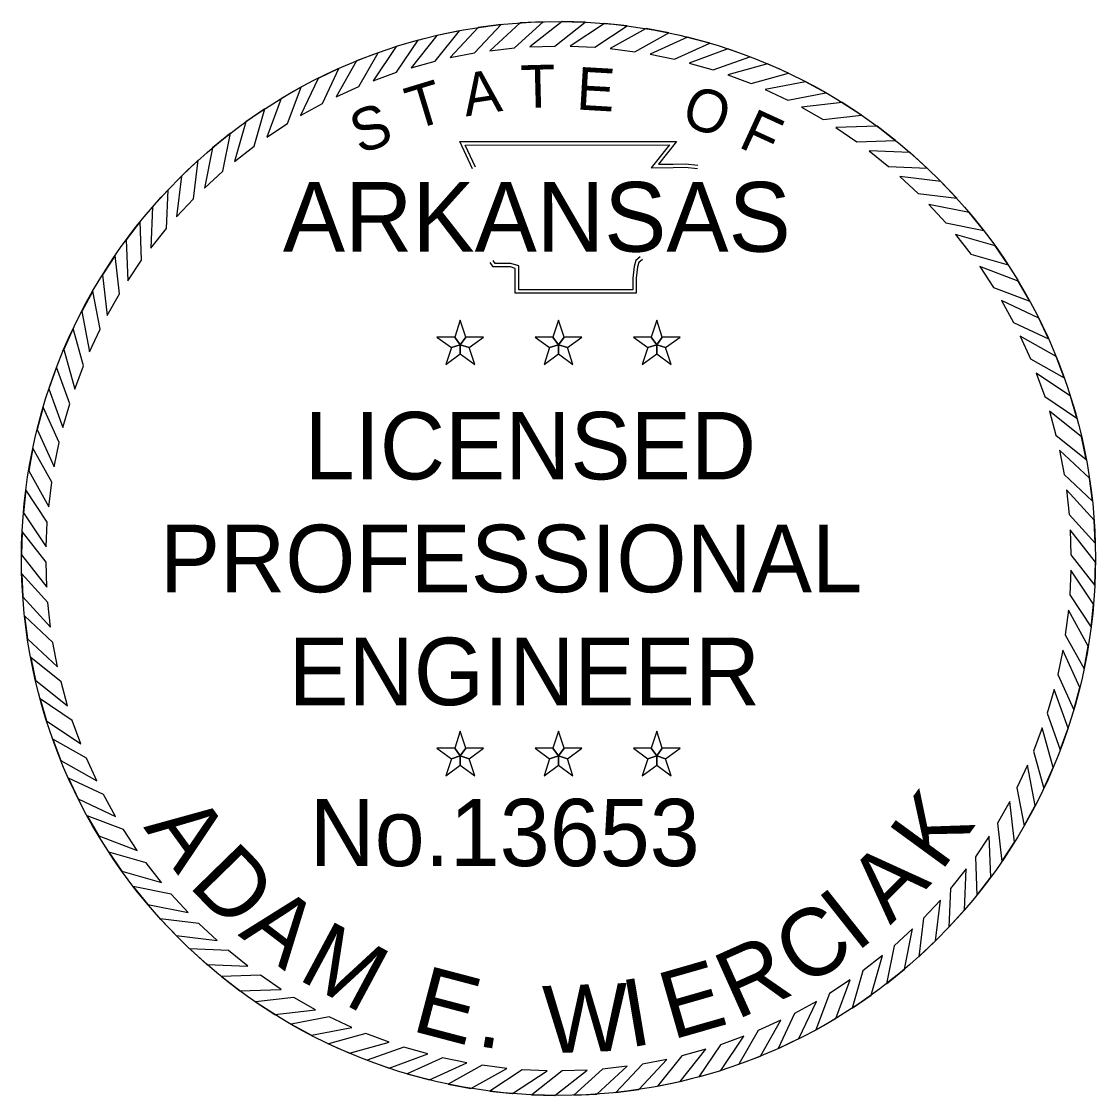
# Model space of a CAD drawing. Extents: x 0 to 19, y -0.6 to 11.3.
# Drawn here: x 17.822 to 19.022, y 6.31 to 7.51 of the extents above; entities that cross this region are included whole.
import ezdxf

# ---------------------------------------------------------------- set-up
doc = ezdxf.new("R2010")
doc.units = 0
for name, color, linetype in [('G-ANNO-STMP', 7, 'Continuous'), ('G-No Plot-Stamp-1', 7, 'Continuous'), ('G-No Plot-Stamp-2', 7, 'Continuous')]:
    doc.layers.add(name, color=color, linetype=linetype)

msp = doc.modelspace()

# ---------------------------------------------------------------- linework, layer by layer
at = {"layer": 'G-ANNO-STMP'}
for points in [[(18.3581, 7.5062), (18.3325, 7.5029), (18.3011, 7.4693), (18.3285, 7.4745)], [(18.4051, 7.5094), (18.3793, 7.5081), (18.3454, 7.477), (18.3731, 7.4801)], [(18.4522, 7.5089), (18.4264, 7.5096), (18.3902, 7.4813), (18.418, 7.4822)], [(18.4991, 7.5047), (18.4735, 7.5074), (18.4351, 7.4821), (18.463, 7.4808)], [(18.5456, 7.4968), (18.5202, 7.5016), (18.48, 7.4793), (18.5077, 7.4758)], [(18.2656, 7.4888), (18.2408, 7.4815), (18.2151, 7.4434), (18.2413, 7.4529)], [(18.3115, 7.4993), (18.2862, 7.494), (18.2576, 7.458), (18.2845, 7.4654)], [(18.5913, 7.4853), (18.5664, 7.4921), (18.5245, 7.473), (18.5518, 7.4674)], [(18.6359, 7.4703), (18.6116, 7.479), (18.5684, 7.4632), (18.5952, 7.4555)], [(18.2206, 7.4747), (18.1965, 7.4655), (18.1738, 7.4255), (18.1992, 7.437)], [(18.1769, 7.4572), (18.1536, 7.4461), (18.1341, 7.4044), (18.1585, 7.4179)], [(18.6793, 7.4518), (18.6557, 7.4624), (18.6114, 7.4501), (18.6375, 7.4402)], [(18.721, 7.43), (18.6984, 7.4423), (18.6532, 7.4336), (18.6784, 7.4217)], [(18.1347, 7.4362), (18.1123, 7.4234), (18.0962, 7.3803), (18.1195, 7.3956)], [(18.7609, 7.4049), (18.7393, 7.419), (18.6936, 7.4138), (18.7178, 7.4)], [(18.0942, 7.412), (18.0729, 7.3975), (18.0603, 7.3533), (18.0823, 7.3704)], [(18.7987, 7.3768), (18.7783, 7.3926), (18.7323, 7.391), (18.7554, 7.3753)], [(18.0558, 7.3848), (18.0357, 7.3686), (18.0266, 7.3235), (18.0472, 7.3423)], [(18.8342, 7.3458), (18.8151, 7.3632), (18.7692, 7.3652), (18.7909, 7.3477)], [(18.0197, 7.3545), (18.0009, 7.3368), (17.9953, 7.2912), (18.0144, 7.3115)], [(18.8672, 7.3122), (18.8495, 7.3309), (18.8038, 7.3365), (18.8242, 7.3175)], [(17.986, 7.3216), (17.9687, 7.3025), (17.9667, 7.2565), (17.9841, 7.2783)], [(18.8974, 7.276), (18.8812, 7.2961), (18.8361, 7.3053), (18.8549, 7.2847)], [(17.955, 7.2861), (17.9393, 7.2657), (17.9409, 7.2197), (17.9565, 7.2428)], [(18.9247, 7.2376), (18.9101, 7.2589), (18.8659, 7.2716), (18.883, 7.2496)], [(17.9269, 7.2483), (17.9128, 7.2267), (17.918, 7.181), (17.9318, 7.2052)], [(18.9489, 7.1972), (18.936, 7.2196), (18.893, 7.2357), (18.9083, 7.2124)], [(17.9019, 7.2084), (17.8895, 7.1857), (17.8983, 7.1406), (17.9102, 7.1658)], [(18.9698, 7.155), (18.9588, 7.1783), (18.9171, 7.1977), (18.9305, 7.1733)], [(17.88, 7.1666), (17.8695, 7.1431), (17.8818, 7.0988), (17.8916, 7.1248)], [(18.3125, 7.1485), (18.3187, 7.157), (18.3125, 7.176), (18.3064, 7.157)], [(18.4222, 7.1485), (18.4284, 7.157), (18.4222, 7.176), (18.4161, 7.157)], [(18.532, 7.1485), (18.5381, 7.157), (18.532, 7.176), (18.5258, 7.157)], [(18.3125, 7.1485), (18.3064, 7.157), (18.2864, 7.157), (18.3026, 7.1453)], [(18.3125, 7.1485), (18.3225, 7.1453), (18.3386, 7.157), (18.3187, 7.157)], [(18.4222, 7.1485), (18.4161, 7.157), (18.3962, 7.157), (18.4123, 7.1453)], [(18.4222, 7.1485), (18.4322, 7.1453), (18.4483, 7.157), (18.4284, 7.157)], [(18.532, 7.1485), (18.5258, 7.157), (18.5059, 7.157), (18.522, 7.1453)], [(18.532, 7.1485), (18.5419, 7.1453), (18.5581, 7.157), (18.5381, 7.157)], [(18.9874, 7.1113), (18.9782, 7.1354), (18.9382, 7.158), (18.9496, 7.1326)], [(18.3125, 7.1485), (18.3026, 7.1453), (18.2964, 7.1263), (18.3125, 7.1381)], [(18.3125, 7.1485), (18.3125, 7.1381), (18.3286, 7.1263), (18.3225, 7.1453)], [(18.4222, 7.1485), (18.4123, 7.1453), (18.4061, 7.1263), (18.4222, 7.1381)], [(18.4222, 7.1485), (18.4222, 7.1381), (18.4384, 7.1263), (18.4322, 7.1453)], [(18.532, 7.1485), (18.522, 7.1453), (18.5158, 7.1263), (18.532, 7.1381)], [(18.532, 7.1485), (18.532, 7.1381), (18.5481, 7.1263), (18.5419, 7.1453)], [(17.8615, 7.1233), (17.8529, 7.099), (17.8686, 7.0558), (17.8764, 7.0825)], [(19.0015, 7.0663), (18.9942, 7.0911), (18.9561, 7.1168), (18.9655, 7.0905)], [(17.8465, 7.0786), (17.8398, 7.0537), (17.8588, 7.0119), (17.8645, 7.0392)], [(19.012, 7.0204), (19.0067, 7.0456), (18.9707, 7.0742), (18.978, 7.0474)], [(17.835, 7.0329), (17.8303, 7.0076), (17.8526, 6.9674), (17.856, 6.995)], [(19.0188, 6.9738), (19.0155, 6.9993), (18.9819, 7.0307), (18.9871, 7.0033)], [(17.8272, 6.9865), (17.8244, 6.9608), (17.8498, 6.9225), (17.8511, 6.9503)], [(19.022, 6.9267), (19.0207, 6.9525), (18.9897, 6.9864), (18.9927, 6.9587)], [(17.823, 6.9396), (17.8222, 6.9138), (17.8505, 6.8775), (17.8497, 6.9054)], [(19.0215, 6.8796), (19.0223, 6.9054), (18.994, 6.9417), (18.9948, 6.9138)], [(17.8225, 6.8925), (17.8237, 6.8667), (17.8548, 6.8328), (17.8518, 6.8605)], [(19.0173, 6.8327), (19.0201, 6.8584), (18.9947, 6.8967), (18.9934, 6.8689)], [(17.8256, 6.8454), (17.829, 6.8199), (17.8626, 6.7885), (17.8574, 6.8159)], [(19.0095, 6.7863), (19.0142, 6.8116), (18.9919, 6.8518), (18.9884, 6.8242)], [(18.998, 6.7406), (19.0047, 6.7655), (18.9856, 6.8073), (18.98, 6.78)], [(17.8325, 6.7988), (17.8378, 6.7736), (17.8738, 6.745), (17.8665, 6.7718)], [(18.9829, 6.6959), (18.9916, 6.7202), (18.9759, 6.7634), (18.9681, 6.7367)], [(17.843, 6.7529), (17.8503, 6.7281), (17.8884, 6.7024), (17.879, 6.7287)], [(18.9645, 6.6526), (18.975, 6.6761), (18.9627, 6.7204), (18.9529, 6.6944)], [(18.3125, 6.6891), (18.3187, 6.6976), (18.3125, 6.7165), (18.3064, 6.6976)], [(18.4222, 6.6891), (18.4284, 6.6976), (18.4222, 6.7165), (18.4161, 6.6976)], [(18.532, 6.6891), (18.5381, 6.6976), (18.532, 6.7165), (18.5258, 6.6976)], [(17.8571, 6.7079), (17.8663, 6.6838), (17.9063, 6.6612), (17.8949, 6.6866)], [(18.3125, 6.6891), (18.3064, 6.6976), (18.2864, 6.6976), (18.3026, 6.6858)], [(18.3125, 6.6891), (18.3225, 6.6858), (18.3386, 6.6976), (18.3187, 6.6976)], [(18.4222, 6.6891), (18.4161, 6.6976), (18.3962, 6.6976), (18.4123, 6.6858)], [(18.4222, 6.6891), (18.4322, 6.6858), (18.4483, 6.6976), (18.4284, 6.6976)], [(18.532, 6.6891), (18.5258, 6.6976), (18.5059, 6.6976), (18.522, 6.6858)], [(18.532, 6.6891), (18.5419, 6.6858), (18.5581, 6.6976), (18.5381, 6.6976)], [(18.3125, 6.6891), (18.3026, 6.6858), (18.2964, 6.6669), (18.3125, 6.6786)], [(18.3125, 6.6891), (18.3125, 6.6786), (18.3286, 6.6669), (18.3225, 6.6858)], [(18.4222, 6.6891), (18.4123, 6.6858), (18.4061, 6.6669), (18.4222, 6.6786)], [(18.4222, 6.6891), (18.4222, 6.6786), (18.4384, 6.6669), (18.4322, 6.6858)], [(18.532, 6.6891), (18.522, 6.6858), (18.5158, 6.6669), (18.532, 6.6786)], [(18.532, 6.6891), (18.532, 6.6786), (18.5481, 6.6669), (18.5419, 6.6858)], [(18.9426, 6.6108), (18.955, 6.6335), (18.9462, 6.6786), (18.9343, 6.6534)], [(17.8747, 6.6642), (17.8857, 6.6409), (17.9274, 6.6215), (17.914, 6.6459)], [(18.9176, 6.5709), (18.9317, 6.5925), (18.9265, 6.6382), (18.9127, 6.614)], [(17.8956, 6.622), (17.9085, 6.5996), (17.9515, 6.5835), (17.9362, 6.6068)], [(18.8895, 6.5331), (18.9052, 6.5535), (18.9036, 6.5995), (18.888, 6.5764)], [(17.9198, 6.5816), (17.9344, 6.5603), (17.9786, 6.5476), (17.9615, 6.5696)], [(18.8585, 6.4976), (18.8758, 6.5167), (18.8778, 6.5627), (18.8604, 6.5409)], [(17.9471, 6.5432), (17.9633, 6.5231), (18.0083, 6.5139), (17.9896, 6.5345)], [(18.8248, 6.4647), (18.8436, 6.4824), (18.8492, 6.528), (18.8301, 6.5077)], [(17.9773, 6.507), (17.995, 6.4883), (18.0407, 6.4827), (18.0203, 6.5017)], [(18.7887, 6.4344), (18.8088, 6.4506), (18.8179, 6.4957), (18.7973, 6.4769)], [(18.0103, 6.4734), (18.0294, 6.456), (18.0753, 6.454), (18.0536, 6.4715)], [(18.7503, 6.4072), (18.7716, 6.4217), (18.7842, 6.4659), (18.7622, 6.4488)], [(18.0458, 6.4424), (18.0662, 6.4266), (18.1122, 6.4282), (18.0891, 6.4439)], [(18.7098, 6.383), (18.7322, 6.3958), (18.7483, 6.4389), (18.725, 6.4236)], [(18.0836, 6.4143), (18.1052, 6.4002), (18.1509, 6.4054), (18.1267, 6.4192)], [(18.6676, 6.362), (18.6909, 6.3731), (18.7104, 6.4148), (18.6859, 6.4013)], [(18.1235, 6.3892), (18.1461, 6.3769), (18.1913, 6.3856), (18.166, 6.3975)], [(18.6239, 6.3445), (18.648, 6.3537), (18.6707, 6.3937), (18.6453, 6.3822)], [(18.1652, 6.3674), (18.1888, 6.3568), (18.2331, 6.3691), (18.207, 6.379)], [(18.5789, 6.3304), (18.6037, 6.3377), (18.6294, 6.3758), (18.6032, 6.3663)], [(18.2086, 6.3489), (18.2329, 6.3402), (18.2761, 6.356), (18.2493, 6.3637)], [(18.533, 6.3199), (18.5583, 6.3252), (18.5869, 6.3612), (18.56, 6.3538)], [(18.2532, 6.3339), (18.2781, 6.3271), (18.32, 6.3462), (18.2927, 6.3518)], [(18.4864, 6.313), (18.512, 6.3163), (18.5434, 6.3499), (18.516, 6.3447)], [(18.2989, 6.3224), (18.3243, 6.3176), (18.3645, 6.3399), (18.3368, 6.3434)], [(18.3454, 6.3145), (18.371, 6.3118), (18.4094, 6.3371), (18.3815, 6.3384)], [(18.3923, 6.3103), (18.4181, 6.3096), (18.4543, 6.3379), (18.4265, 6.337)], [(18.4394, 6.3098), (18.4652, 6.3111), (18.4991, 6.3422), (18.4714, 6.3391)]]:
    msp.add_lwpolyline(points, close=True, dxfattribs=at)
for points in [[(18.3261, 7.3451), (18.3121, 7.3754), (18.5542, 7.3755), (18.5339, 7.3501), (18.5504, 7.3503), (18.5641, 7.3505), (18.5778, 7.349)], [(18.3296, 7.3467), (18.3181, 7.3716), (18.5462, 7.3717), (18.5259, 7.3462), (18.5504, 7.3465), (18.5639, 7.3467), (18.5774, 7.3452)], [(18.516, 7.2437), (18.5119, 7.2403), (18.5105, 7.2353), (18.5091, 7.2227), (18.5091, 7.206), (18.374, 7.206), (18.374, 7.2286), (18.374, 7.2336), (18.3686, 7.2353), (18.3493, 7.2353), (18.3459, 7.2405)], [(18.5136, 7.2466), (18.5085, 7.2425), (18.5067, 7.236), (18.5053, 7.223), (18.5053, 7.2099), (18.3779, 7.2099), (18.3779, 7.2286), (18.3779, 7.2365), (18.3691, 7.2391), (18.3514, 7.2391), (18.3491, 7.2426)]]:
    msp.add_lwpolyline(points, dxfattribs=at)
at = {"layer": 'G-No Plot-Stamp-1'}
msp.add_circle((18.4222, 6.9096), 0.6, dxfattribs=at)
at = {"layer": 'G-No Plot-Stamp-2'}
msp.add_circle((18.4222, 6.9096), 0.6, dxfattribs=at)

# ---------------------------------------------------------------- texts
at = {"layer": 'G-ANNO-STMP'}
for s, height, rotation, p in [('A', 0.0477, 8.6788, (18.3187, 7.4034)), ('T', 0.0477, 1.4789, (18.3804, 7.4129)), ('E', 0.0477, 356.672, (18.4415, 7.4114)), ('T', 0.0477, 16.9015, (18.2608, 7.3882)), ('O', 0.0477, 341.2218, (18.5574, 7.395)), ('S', 0.0477, 19.7726, (18.2001, 7.361)), ('F', 0.0477, 335.3628, (18.6218, 7.3699)), ('K', 0.0754, 53.8471, (18.8495, 6.5585)), ('A', 0.0754, 305.982, (17.958, 6.6093)), ('D', 0.0754, 314.3022, (18.0075, 6.5441)), ('A', 0.0754, 45.185, (18.7929, 6.4994)), ('A', 0.0754, 322.6223, (18.0634, 6.4889)), ('I', 0.0754, 38.4057, (18.7549, 6.4687)), ('C', 0.0754, 32.1396, (18.695, 6.4289)), ('M', 0.0754, 331.7969, (18.1293, 6.4402)), ('R', 0.0754, 24.1616, (18.6211, 6.3937)), ('E', 0.0754, 16.0125, (18.5491, 6.3716)), ('E', 0.0754, 345.2782, (18.2564, 6.3823)), ('W', 0.0754, 2.1127, (18.4063, 6.3565)), ('I', 0.0754, 9.5753, (18.5011, 6.363)), ('.', 0.0754, 350.8583, (18.3296, 6.3653))]:
    msp.add_text(s, height=height, rotation=rotation, dxfattribs=at).set_placement(p)
for s, height, p in [('ARKANSAS', 0.07792, (18.1143, 7.2524)), ('LICENSED', 0.07543, (18.1385, 6.998)), ('PROFESSIONAL', 0.075433, (17.9768, 6.8719)), ('ENGINEER', 0.07543, (18.1205, 6.7457)), ('No.13653', 0.07514, (18.1443, 6.5659))]:
    msp.add_text(s, height=height, dxfattribs=at).set_placement(p)

doc.saveas('drawing.dxf')
